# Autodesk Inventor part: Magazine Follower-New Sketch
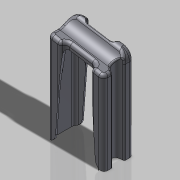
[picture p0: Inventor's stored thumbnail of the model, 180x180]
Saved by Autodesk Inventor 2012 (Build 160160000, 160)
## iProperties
Category: Sten MK II Magazine
Company: MH Vaaben Teknik
Created: 2011-12
Part Number: Magazine Follower-New Sketch
Material: Carbon Steel
Document SubType Name: Modeling
Designer: Michael Høgh
Density: 7.87 g/cm^3
Project: Sten MK II
Engineer: MH Vaaben Teknik
Mass: 26.1964 g
Surface Area: 79.4791 cm^2
Volume: 3.32864 cm^3
Author: Michael Høgh
Title: Magazine Follower
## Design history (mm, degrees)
sketch "Sketch1"
  geometry: L1 (17.4, 9.4)-(17.4, -9.4); L2 (-17.4, -8.3)-(-17.4, 8.3); L3 (-17.4, 8.3)-(26.503, 9.688); L4 (-17.4, -8.3)-(24.847, -9.635); 2 further points
  constraints: 8 end point, 2 point on line, 1 horizontal alignment, 1 midpoint, 1 parallel
  dimensions: "d72" = 16.6 distance of L2.start L2.end; "d73" = 34.8 distance between parallel lines of L1 L2; "d74" = 18.8 distance of L1.start L1.end; "d75" = 9.4 vertical distance of point (0, 0) L1.start; "d76" = 8.3 vertical distance of L2.end point (0, 0)
extrude "Extrusion1" new body sketch "Sketch1" distance "d2" = 60.5; taper "d3" = 0 deg
workplane "Work Plane1"
workplane "Work Plane2"
sketch "Sketch9"
  geometry: L1 (0, -34.8)-(60.5, -34.8) reference; L2 (60.5, 0)-(60.5, -34.8) reference; L3 (0, 0)-(60.5, 0) reference; L4 (0, -34.8)-(0, 0) reference; L5 (60.5, -28.333)-(56.922, -5.494); L6 (50.5, 0)-(0, 0); L7 (0, 0)-(0, -34.8); L8 (0, -34.8)-(54.5, -34.8); A1 r 6 centre (54.5, -28.8) between (54.5, -34.8) and (60.428, -27.871); A2 r 6.5 centre (50.5, -6.5) between (56.922, -5.494) and (50.5, 0); 1 further point
  constraints: 8 end point, 6 tangent, 4 point on circle, 4 point on line, 2 centre point, 2 collinear
  dimensions: "d78" = 12 diameter of A1; "d79" = 13 diameter of A2; "d80" = 50.5 distance from line of A2.centre L4
extrude "Extrusion9" cut sketch "Sketch9" stored distance "d81" = 10; taper "d82" = 0 deg
fillet "Fillet22" dims "d105" = 2.8
workplane "Work Plane3"
sketch "Sketch14"
  geometry: L1 (-0.091, -0.447)-(-0.091, -50.338) reference; L2 (-2.89, -49.891)-(-15.91, -49.891) reference; L3 (-18.709, -50.338)-(-18.709, -0.447) reference; L4 (1.519, 0.009)-(-8.421, 0.009); L5 (1.519, 8.009)-(1.519, 0.009); L6 (-14.481, 8.009)-(-18.709, 8.009); L7 (-18.709, 8.009)-(-18.709, 2.559); A1 r 2.85 centre (-15.859, 2.559) between (-18.709, 2.559) and (-13.461, 4.1); A2 r 8 centre (-6.481, 8.009) between (-13.461, 4.1) and (-6.481, 0.009); A3 r 8 centre (-6.481, 8.009) between (1.519, 8.009) and (-14.481, 8.009); 1 further point
  constraints: 8 end point, 6 point on circle, 4 tangent, 3 centre point, 3 perpendicular, 1 point on line
  dimensions: "d107" = 5.7 diameter of A1; "d108" = 6.39 distance from line of A2.centre L1; "d109" = 57.9 distance from line of A2.centre L2; "d110" = 52.45 distance from line of A1.centre L2
extrude "Extrusion13" cut sketch "Sketch14" stored distance "d111" = 0; taper "d112" = 0 deg
fillet "Fillet23" dims "d113" = 2
sketch "Sketch15"
  geometry: L1 (-17.4, 2.632)-(-17.4, -2.919) reference; C1 r 3.6 at (-17.4, -0.143); 1 further point
  constraints: 1 centre point, 1 midpoint
  dimensions: "d114" = 7.2 diameter of C1
extrude "Extrusion14" cut sketch "Sketch15" stored distance "d115" = 5; taper "d116" = 0 deg
fillet "Fillet24" dims "d117" = 1
workplane "Work Plane Left"
sketch "Sketch18"
  geometry: L1 (-17.4, 4.346)-(-17.4, 6.51) reference; L2 (-6.9, 5.357)-(6.6, 5.357); L3 (-6.9, -5.643)-(6.6, -5.643); L4 (-6.9, 10.957)-(6.6, 10.957); L5 (-6.9, -11.243)-(6.6, -11.243); A1 r 3.6 centre (-17.4, -0.143) between (-16.617, -3.657) and (-16.617, 3.37) reference; A2 r 2.8 centre (-6.9, 8.157) between (-6.9, 10.957) and (-6.9, 5.357); A3 r 2.8 centre (-6.9, -8.443) between (-6.9, -11.243) and (-6.9, -5.643); A4 r 2.8 centre (6.6, 8.157) between (6.6, 10.957) and (6.6, 5.357); A5 r 2.8 centre (6.6, -8.443) between (6.6, -11.243) and (6.6, -5.643); 1 further point
  constraints: 8 end point, 8 point on circle, 6 tangent, 4 centre point, 1 parallel, 1 perpendicular
  dimensions: "d139" = 5.5 distance from line of L2 A1.centre; "d140" = 5.5 distance from line of A1.centre L3; "d141" = 5.6 diameter of A2; "d144" = 5.6 diameter of A3; "d147" = 5.6 diameter of A4; "d148" = 13.5 distance of A4.centre A2.centre; "d149" = 5.6 diameter of A5; "d150" = 13.5 distance of A5.centre A3.centre; "d168" = 24 horizontal distance of A4.centre A1.centre; "d169" = 24 horizontal distance of A5.centre A1.centre
extrude "Extrusion16" cut sketch "Sketch18" stored distance "d151" = 10; taper "d152" = 0 deg
fillet "Fillet25" dims "d153" = 0.37
fillet "Fillet26" dims "d154" = 0.37
fillet "Fillet27" dims "d155" = 2
shell "Shell4" dims "d156" = 0.87
sketch "Sketch19"
  geometry: L1 (0, -29.2)-(0, 0); L2 (0, 2.888)-(-48.798, 2.888); L3 (-53.623, -31.912)-(0, -31.912) reference; L4 (-50.665, -21.362)-(-48.513, -7.628); L5 (-53.502, -29.168)-(-48.927, 0.032); L6 (-63.007, -41.996)-(-54.094, 14.891) reference; L7 (-48.836, -23.666)-(-4.632, -26.925); L8 (-45.523, -4.889)-(-4.66, -2.1); L9 (0, -31.912)-(0, 2.888); A1 r 2 centre (-48.689, -21.672) between (-50.665, -21.362) and (-48.836, -23.666); A2 r 3.25 centre (-45.302, -8.132) between (-45.523, -4.889) and (-48.513, -7.628); A3 r 5 centre (-5, -31.912) between (0, -31.912) and (-4.632, -26.925); A4 r 5 centre (-5, 2.888) between (-4.66, -2.1) and (0, 2.888); 2 further points
  constraints: 18 end point, 10 tangent, 8 point on circle, 4 centre point, 2 parallel, 2 point on line, 1 horizontal, 1 perpendicular, 1 other
  dimensions: "d157" = 4 diameter of A1; "d158" = 6.5 diameter of A2; "d159" = 10.24 distance from line of A1.centre L3; "d160" = 11.02 distance from line of L2 A2.centre; "d161" = 9 distance between parallel lines of L4 L6; "d162" = 0 distance from line of A3.centre L3; "d163" = 0 distance from line of L2 A4.centre; "d165" = 3.90465 deg angle of L2 L8 (derived); "d166" = 5 radius of A3; "d167" = 5 radius of A4
extrude "Extrusion17" cut sketch "Sketch19" stored distance "d171" = 10; taper "d172" = 0 deg
workplane "Work Plane7"
sketch "Sketch20"
  geometry: L1 (13.887, -0.87)-(2.713, -0.87); L2 (13.887, -0.87)-(2.713, -0.87) reference; L3 (13.073, -10.5)-(13.073, -24.3); L4 (13.073, -10.8)-(13.073, -24.3) reference; L5 (3.813, -10.546)-(3.813, -24.301); L6 (4.239, -30.859)-(4.239, -5.05) reference; L7 (15.816, -2.742)-(15.931, -6.375); L8 (15.931, -6.375)-(15.887, -4.986) reference; L9 (0.644, -7.158)-(0.784, -2.739); L10 (16.643, -28.904)-(16.739, -31.939); L11 (16.672, -29.812)-(16.739, -31.939) reference; L12 (14.81, -33.93)-(12.933, -33.93); L13 (12.933, -33.93)-(14.81, -33.93) reference; L14 (3.954, -33.93)-(1.79, -33.93); L15 (1.79, -33.93)-(3.954, -33.93) reference; L16 (-0.014, -27.984)-(-0.139, -31.939); L17 (-0.139, -31.939)-(-0.072, -29.812) reference; A1 r 3.67 centre (16.743, -10.8) between (14.109, -8.245) and (13.073, -10.8); A2 r 1.93 centre (13.887, -2.8) between (15.816, -2.739) and (13.887, -0.87); A3 r 1.93 centre (2.713, -2.8) between (2.713, -0.87) and (0.784, -2.739) reference; A4 r 1.93 centre (2.713, -2.8) between (2.713, -0.87) and (0.784, -2.739); A5 r 3.701 centre (0.122, -10.822) between (3.813, -10.546) and (0.644, -7.158); A6 r 1.13 centre (14.802, -6.41) between (15.259, -7.444) and (15.931, -6.375); A7 r 4.261 centre (17.087, -11.292) between (15.259, -7.444) and (14.109, -8.245); A8 r 3.49 centre (16.561, -24.432) between (13.073, -24.3) and (15.763, -27.829); A9 r 1.141 centre (15.502, -28.94) between (16.643, -28.904) and (15.763, -27.829); A10 r 1.93 centre (14.81, -32) between (14.81, -33.93) and (16.739, -31.939); A11 r 4.572 centre (8.443, -34.793) between (12.933, -33.93) and (3.954, -33.93); A12 r 1.93 centre (1.79, -32) between (-0.139, -31.939) and (1.79, -33.93) reference; A13 r 1.93 centre (1.79, -32) between (-0.139, -31.939) and (1.79, -33.93); A14 r 3.669 centre (0.144, -24.301) between (-0.014, -27.967) and (3.813, -24.301); 2 further points
  constraints: 24 point on circle, 19 end point, 13 tangent, 12 centre point, 7 collinear, 2 parallel, 1 concentric, 3 other
body "Solid1"
other parameters: "d77" = 90 deg, "d83" = 90 deg, "d84" = 16, "d106" = 16, "d119" = 90 deg, "d173" = 90 deg
